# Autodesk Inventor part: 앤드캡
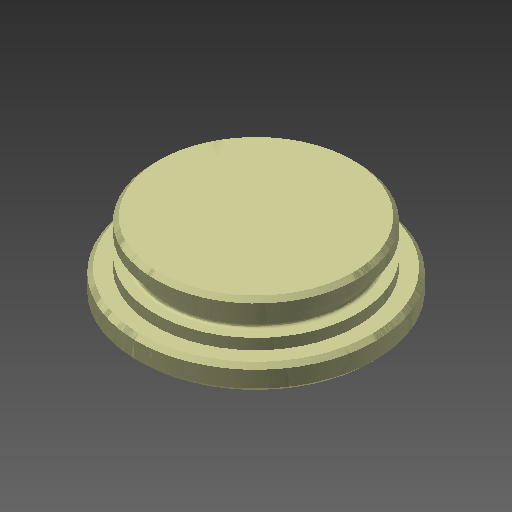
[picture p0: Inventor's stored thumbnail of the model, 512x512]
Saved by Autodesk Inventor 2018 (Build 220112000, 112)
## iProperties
Created: 2023-03
Part Number: 앤드캡
Material: 알루미늄 6061
Document SubType Name: Modeling
Designer: mdu-01
Density: 1 g/cm^3
Appearance: 알루미늄 - 평지(1)
Author: mdu-01
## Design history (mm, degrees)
sketch "스케치1"
  geometry: L1 (0, 0)-(0, 17); L2 (0, 17)-(24, 17); L3 (25, 6)-(28.5, 6); L4 (29.5, 5)-(29.5, 1); L5 (28.5, 0)-(0, 0); L6 (29.5, 1)-(28.5, 0); L7 (24, 17)-(25, 16); L8 (25, 13.35)-(22.8, 13.35); L9 (22, 12.55)-(22, 9.45); L10 (22.8, 8.65)-(25, 8.65); L11 (22, 11)-(25, 11); L12 (25, 16)-(25, 13.35); L13 (25, 8.65)-(25, 6); L14 (25, 9)-(25, 62) reference; L15 (28.5, 6)-(29.5, 5); A1 r 0.8 centre (22.8, 9.45) between (22, 9.45) and (22.8, 8.65); A2 r 0.8 centre (22.8, 12.55) between (22.8, 13.35) and (22, 12.55); 3 further points
  constraints: 31 end point, 8 perpendicular, 6 point on line, 4 parallel, 4 point on circle, 4 tangent, 2 centre point, 2 collinear, 2 vertical, 1 equal radius, 1 midpoint, 2 other
  dimensions: "d0" = 17 distance of L1.end L1.start; "d1" = 11 distance between parallel lines of L3 L2; "d6" = 1 distance of L4.end point (29.5, 0); "d7" = 1 distance of L5.start point (29.5, 0) (= d6); "d8" = 1 distance of L2.end point (25, 17) (= d6); "d9" = 1 distance of L7.end point (25, 17) (= d8); "d11" = 6 distance between parallel lines of L11 L2; "d12" = 4.7 distance between parallel lines of L10 L8; "d13" = 44 diameter of L9 L1; "d15" = 0.8 radius of A2; "d37" = 1 distance of L3.end point (29.5, 6); "d38" = 1 distance of L4.start point (29.5, 6) (= d37); "d39" = 59 diameter of L4 L1
revolve "회전1" sketch "스케치1" stored, may be unused: angle "d16" = 90 deg
node "솔리드1"
